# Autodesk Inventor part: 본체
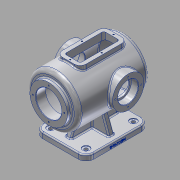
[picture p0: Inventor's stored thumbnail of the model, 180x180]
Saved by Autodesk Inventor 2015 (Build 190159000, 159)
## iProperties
Created: 2021-11
Part Number: 본체
Material: 알루미늄 6061
Document SubType Name: Modeling
Designer: 102879
Density: 2.7 g/cm^3
Appearance: 알루미늄 - 평지
Mass: 3642.31 g
Surface Area: 2489.08 cm^2
Volume: 1349 cm^3
Author: 102879
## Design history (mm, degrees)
sketch "스케치3"
  geometry: L1 (-100, 65)-(-100, 0); L2 (75.993, 65)-(-100, 65); L3 (-100, 0)-(100, 0); A1 r 100 centre (0, 0) between (100, 0) and (75.993, 65); 1 further point
  constraints: 6 end point, 2 horizontal, 2 point on circle, 1 centre point, 1 coincident, 1 midpoint, 1 vertical
  dimensions: "d5" = 100 radius of A1; "d6" = 65 distance from line of point (0, 0) L2; "d10" = 200 dimension on A1 L1
revolve "회전1" sketch "스케치3" stored, may be unused: angle "d11" = 90 deg
sketch "스케치4"
  geometry: C1 r 65 at (0, 0) reference; C2 r 47.5 at (0, 0)
  constraints: 1 centre point, 1 coincident
  dimensions: "d12" = 95 diameter of C2
extrude "돌출2" join sketch "스케치4" distance "d13" = 10; taper "d14" = 0 deg
node "작업 평면1"
sketch "스케치5"
  geometry: L1 (-30, -60)-(30, -60); L2 (30, -60)-(30, 60); L3 (30, 60)-(-30, 60); L4 (-30, 60)-(-30, -60); L5 (-47.5, -110)-(47.5, -110) reference; 1 further point
  constraints: 8 end point, 2 parallel, 1 horizontal, 1 perpendicular
  dimensions: "d16" = 120 distance of L3.end L1.start; "d17" = 60 distance of L1.start L1.end; "d18" = 30 distance from line of L4 point (0, 0); "d26" = 50 distance between parallel lines of L5 L1
extrude "돌출3" join sketch "스케치5" stored distance "d20" = 10; taper "d21" = 0 deg
node "작업 평면2"
sketch "스케치8"
  geometry: L1 (-110, 47.5)-(-100, 47.5) reference; L2 (-100, 47.5)-(-100, 65) reference; L3 (-100, 65)-(-60, 65) reference; L4 (-60, 65)-(-60, 70) reference; L5 (-60, 70)-(60, 70) reference; L6 (60, 70)-(60, 65) reference; L7 (60, 65)-(75.993, 65) reference; L8 (75.993, -65)-(-100, -65) reference; L9 (-100, -65)-(-100, -47.5) reference; L10 (-100, -47.5)-(-110, -47.5) reference; L11 (-110, -47.5)-(-110, 47.5) reference; C1 r 40 at (17, 0); A1 r 100 centre (0, 0) between (75.993, -65) and (75.993, 65) reference; 1 further point
  constraints: 1 centre point, 1 horizontal alignment
  dimensions: "d28" = 80 diameter of C1; "d29" = 127 distance from line of L11 C1.centre
extrude "돌출5" join sketch "스케치8" stored distance "d30" = 150; taper "d31" = 0 deg
sketch "스케치9"
  geometry: L1 (-65, -80)-(65, -80); L2 (65, -80)-(65, 80); L3 (65, 80)-(-65, 80); L4 (-65, 80)-(-65, -80); L5 (-30, -60)-(30, -60) reference; L6 (30, 60)-(-30, 60) reference; 1 further point
  constraints: 8 end point, 2 parallel, 1 horizontal, 1 perpendicular
  dimensions: "d32" = 160 distance of L1.end L2.end; "d33" = 130 distance of L1.start L1.end; "d34" = 65 distance from line of point (0, 0) L2; "d35" = 20 distance between parallel lines of L5 L1; "d36" = 20 distance between parallel lines of L6 L3 (derived)
extrude "돌출6" join sketch "스케치9" distance "d37" = 14; taper "d38" = 0 deg
node "작업 평면3"
sketch "스케치10"
  geometry: L1 (51.397, 114)-(78.603, 114); L2 (78.603, 114)-(115, 14); L3 (130, 14)-(0, 14) reference; L4 (51.397, 114)-(15, 14); L5 (15, 14)-(115, 14); L6 (0, 0)-(0, 14) reference; L7 (130, 0)-(130, 14) reference; 1 further point
  constraints: 8 end point, 2 collinear, 1 horizontal, 1 midpoint
  dimensions: "d41" = 100 distance of L2.end L4.end; "d42" = 20 deg angle of L4 L6; "d43" = 20 deg angle of L7 L2; "d44" = 50 horizontal distance of point (65, 114) L2.end
extrude "돌출7" join sketch "스케치10" stored distance "d45" = 14; taper "d46" = 0 deg
sketch "스케치11"
  geometry: L1 (-23.603, 0)-(-60, -100); L2 (-23.603, 0)-(23.603, 0); L3 (23.603, 0)-(60, -100); L4 (-60, -100)-(60, -100); L5 (80, -100)-(-80, -100) reference; L6 (7, -100)-(7, -55.515) reference; 1 further point
  constraints: 8 end point, 2 horizontal, 1 collinear, 1 midpoint
  dimensions: "d47" = 120 distance of L1.end L3.end; "d48" = 110 deg angle of L5 L3; "d49" = 110 deg angle of L5 L1; "d50" = 53 distance from line of L6 L3.end
extrude "돌출8" join sketch "스케치11" stored distance "d51" = 14; taper "d52" = 0 deg
sketch "스케치12"
  geometry: L1 (-110, 47.5)-(-100, 47.5) reference; L2 (-100, 47.5)-(-100, 65) reference; L3 (-100, 65)-(-60, 65) reference; L4 (-60, 65)-(-60, 70) reference; L5 (-60, 70)-(60, 70) reference; L6 (60, 70)-(60, 65) reference; L7 (60, 65)-(75.993, 65) reference; L8 (75.993, -65)-(47.261, -65) reference; L9 (47.261, -65)-(60, -100) reference; L10 (60, -100)-(80, -100) reference; L11 (80, -100)-(80, -114) reference; L12 (80, -114)-(-80, -114) reference; L13 (-80, -114)-(-80, -100) reference; L14 (-80, -100)-(-60, -100) reference; L15 (-60, -100)-(-47.261, -65) reference; L16 (-47.261, -65)-(-100, -65) reference; L17 (-100, -65)-(-100, -47.5) reference; L18 (-100, -47.5)-(-110, -47.5) reference; L19 (-110, -47.5)-(-110, 47.5) reference; L20 (71.239, 55)-(-85, 55); L21 (-85, 55)-(-85, 0); L22 (-85, 0)-(90, 0); A1 r 100 centre (0, 0) between (75.993, -65) and (75.993, 65) reference; A2 r 90 centre (0, 0) between (90, 0) and (71.239, 55)
  constraints: 6 end point, 2 horizontal, 2 point on circle, 1 centre point, 1 perpendicular, 1 point on line
  dimensions: "d53" = 10 radial gap between concentric circles of A1 A2; "d54" = 10 distance between parallel lines of L7 L20; "d55" = 25 distance between parallel lines of L19 L21
revolve "회전2" sketch "스케치12" stored, may be unused: angle "d56" = 90 deg
sketch "스케치13"
  geometry: C1 r 47.5 at (0, 0) reference; C2 r 32.5 at (0, 0)
  constraints: 1 centre point, 1 coincident
  dimensions: "d57" = 65 diameter of C2
extrude "돌출9" cut sketch "스케치13" distance "d58" = 25; taper "d59" = 0 deg
sketch "스케치14"
  geometry: C1 r 40 at (0, 0) reference; 1 further point
hole "구멍1" sketch "스케치14" at (0, 0) diameter "d61" = 42; stored, may be unused: countersink angle "d65" = 90 deg, drill point angle "d67" = 118 deg; dims "d62" = 6, "d63" = 52, "d64" = 18, "d66" = 8
sketch "스케치15"
  geometry: C1 r 21 at (0, 0) reference; C2 r 40 at (0, 0) reference; C3 r 26 at (0, 0); 1 further point
  constraints: 1 centre point, 1 coincident
  dimensions: "d68" = 52 diameter of C3
extrude "돌출10" cut sketch "스케치15" distance "d69" = 18; taper "d70" = 0 deg
sketch "스케치16"
  geometry: L1 (-30, -60)-(30, -60) reference; L2 (30, -60)-(30, 60) reference; L3 (30, 60)-(-30, 60) reference; L4 (-30, 60)-(-30, -60) reference; L5 (-20, -50)-(20, -50); L6 (20, -50)-(20, 50); L7 (20, 50)-(-20, 50); L8 (-20, 50)-(-20, -50); 1 further point
  constraints: 8 end point, 3 other
  dimensions: "d71" = 10 distance between parallel lines of L4 L8
extrude "돌출11" cut sketch "스케치16" distance "d72" = 30; taper "d73" = 0 deg
fillet "모깎기1" dims "d74" = 5
fillet "모깎기2" dims "d75" = 15
fillet "모깎기3" dims "d76" = 10
fillet "모깎기4" dims "d77" = 3
fillet "모깎기5" dims "d78" = 20
fillet "모깎기6" dims "d79" = 3
sketch "스케치17"
  geometry: C1 r 32.5 at (0, 0) reference; 1 further point
  constraints: 1 vertical alignment
  dimensions: "d80" = 40 distance of C1.centre point (0, 40)
hole "구멍2" sketch "스케치17" at (0, 40) diameter "d81" = 3.242; stored, may be unused: countersink angle "d85" = 90 deg, drill point angle "d87" = 118 deg; dims "d82" = 11, "d83" = 52, "d84" = 18, "d86" = 13
sketch "스케치18"
  geometry: C1 r 26 at (0, 0) reference; 2 further points
  constraints: 1 horizontal alignment
  dimensions: "d91" = 32.5 distance of C1.centre point (-32.5, 0)
hole "구멍3" sketch "스케치18" at (-32.5, 0) diameter "d92" = 3.242; stored, may be unused: countersink angle "d96" = 90 deg, drill point angle "d98" = 118 deg; dims "d93" = 11, "d94" = 52, "d95" = 18, "d97" = 13
sketch "스케치19"
  geometry: L1 (15, 60)-(-15, 60) reference; 2 further points
  constraints: 1 vertical alignment
  dimensions: "d102" = 5 distance from line of L1 point (0, 55)
hole "구멍4" sketch "스케치19" at (0, 55) diameter "d103" = 3.242; stored, may be unused: countersink angle "d107" = 90 deg, drill point angle "d109" = 118 deg; dims "d104" = 9, "d105" = 52, "d106" = 18, "d108" = 11
sketch "스케치20"
  geometry: C1 r 1.621 at (0, -55) reference; 2 further points
  dimensions: "d113" = 25 distance of point (0, 0) point (-25, 0); "d114" = 55 vertical distance of C1.centre point (-25, 0)
hole "구멍5" sketch "스케치20" at (-25, 0) diameter "d115" = 3.242; stored, may be unused: countersink angle "d119" = 90 deg, drill point angle "d121" = 118 deg; dims "d116" = 9, "d117" = 52, "d118" = 18, "d120" = 11
sketch "스케치21"
  geometry: A1 r 20 centre (45, -60) between (45, -80) and (65, -60) reference; 1 further point
hole "구멍6" sketch "스케치21" at (45, -60) diameter "d125" = 9; stored, may be unused: countersink angle "d129" = 90 deg, drill point angle "d131" = 118 deg; dims "d126" = 9, "d127" = 18, "d128" = 2, "d130" = 9
fillet "모깎기7" dims "d138" = 3
sketch "스케치22"
  geometry: L1 (0, 0)-(0, 120) reference; L2 (-11, 120)-(0, 120) reference; 2 further points
  constraints: 1 other
  dimensions: "d139" = 5 distance from line of L1 point (-5, 60); "d140" = 60 distance from line of L2 point (-5, 60)
feature "엠보싱1" sketch "스케치22" dims "d20" = 10, "d141" = 0.5, "d142" = 0
chamfer "모따기1" distance "d143" = 1; stored, may be unused: second distance "d144" = 2, angle "d145" = 45 deg
fillet "모깎기8" dims "d146" = 3
node "솔리드2"
pattern_circular "원형 패턴1" dims angle "d89" = 360 deg
pattern_circular "원형 패턴2" dims angle "d100" = 360 deg
mirror "대칭1"
pattern_linear "직사각형 패턴1" dims "d112" = 110
pattern_linear "직사각형 패턴2" dims "d124" = 50
pattern_linear "직사각형 패턴3" dims "d134" = 90
node "절단 모서리 투영1"
node "절단 모서리 투영2"
other parameters: "d25" = -114
